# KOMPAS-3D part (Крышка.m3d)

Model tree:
1. Плоскость XY
2. Плоскость ZX
3. Плоскость ZY
4. Ось X
5. Ось Y
6. Ось Z
7. Начало координат
8. Эскиз:1
9. Операция выдавливания:1
     Расстояние 1 = 40; Расстояние 2 = 10
10. Эскиз:2
11. Вырезать элемент выдавливания:1
     Расстояние 2 = 10; Расстояние 1 = 37
12. Эскиз:3
13. Операция выдавливания:2
     Расстояние 1 = 35; Расстояние 2 = 10
14. Эскиз:4
15. Операция выдавливания:3
     Расстояние 1 = 25; Расстояние 2 = 10
16. Эскиз:5
17. Операция выдавливания:4
     Расстояние 1 = 12; Расстояние 2 = 10
18. Эскиз:6
19. Операция выдавливания:5
     Расстояние 1 = 34; Расстояние 2 = 10
20. Эскиз:7
21. Вырезать элемент выдавливания:2
     Расстояние 2 = 10; Расстояние 1 = 2

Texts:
  Линия-выноска #1
  Линия-выноска #2
  Линия-выноска #3
  Отклонения формы и база
  Марка координационной оси
  Марка/позиционное обозначение с линией-выноской
  Марка/позиционное обозначение на линии
  Марка/позиционное обозначение без линии-выноски
  Текст на чертеже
